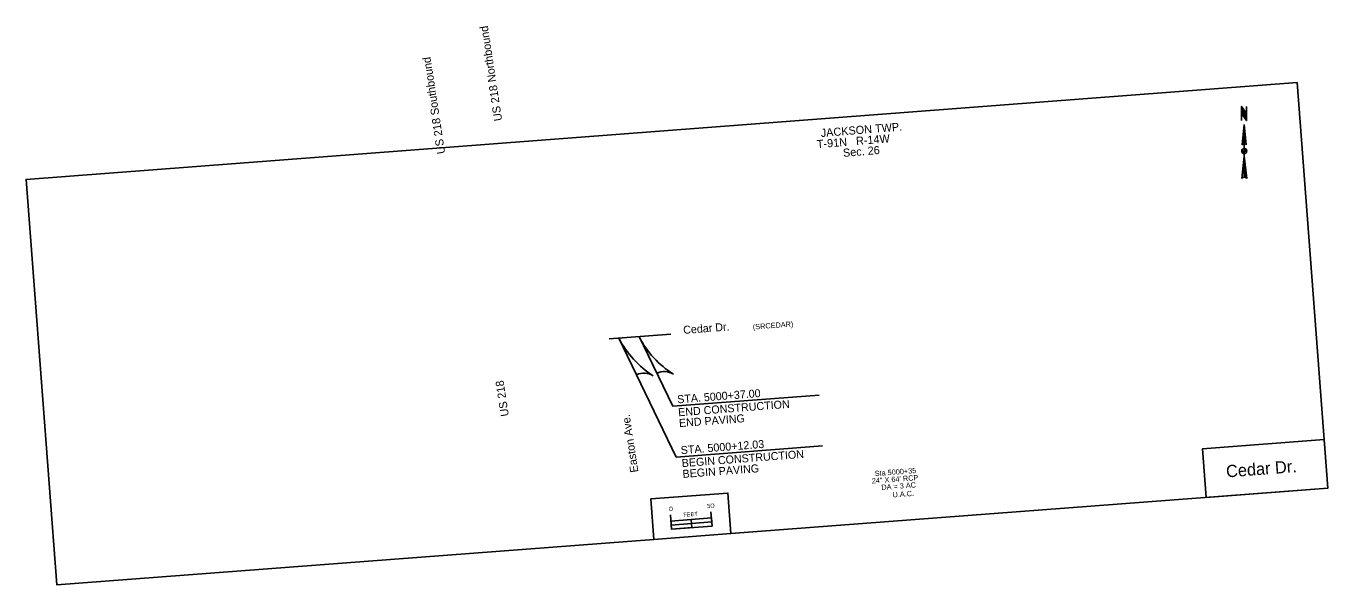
# Model space of a CAD drawing. Extents: x 5197058 to 5310156, y 3593077 to 3706690.
# Drawn here: x 5197058 to 5198659, y 3706003 to 3706690 of the extents above; entities that cross this region are included whole.
import ezdxf

# ---------------------------------------------------------------- set-up
doc = ezdxf.new("R2010")
doc.units = 0
for name, color, linetype in [('dsnAlignment', 7, 'Continuous'), ('dsnCellsScaleBlock', 7, 'Continuous'), ('dsnNonPlotable', 7, 'Continuous'), ('dsnTextCulvertProp', 7, 'Continuous'), ('dsnTextNote', 7, 'Continuous'), ('dsnTextOverlapEven', 7, 'Continuous'), ('dsnTextOverlapOdd', 7, 'Continuous'), ('phoTxtDrainage', 7, 'Continuous'), ('phoTxtTownSecRange', 7, 'Continuous')]:
    doc.layers.add(name, color=color, linetype=linetype)

msp = doc.modelspace()

# ---------------------------------------------------------------- linework, layer by layer
at = {"layer": 'dsnAlignment'}
msp.add_line((5197774.9, 3706305.5), (5197850.9, 3706311.3), dxfattribs=at)
at = {"layer": 'dsnCellsScaleBlock'}
msp.add_line((5197876.6, 3706073.6), (5197875.8, 3706083.5), dxfattribs=at)
msp.add_line((5197876.6, 3706073.6), (5197875.8, 3706083.5), dxfattribs=at)
for points in [[(5197826.2, 3706108.8), (5197921, 3706116), (5197924.7, 3706066.2), (5197830, 3706059)], [(5197826.2, 3706108.8), (5197921, 3706116), (5197924.7, 3706066.2), (5197830, 3706059)], [(5197876.2, 3706078.6), (5197901.1, 3706080.5), (5197900.7, 3706085.4), (5197875.8, 3706083.5)], [(5197851.6, 3706071.7), (5197876.6, 3706073.6), (5197876.2, 3706078.6), (5197851.2, 3706076.7)]]:
    msp.add_lwpolyline(points, close=True, dxfattribs=at)
for points in [[(5197850.3, 3706089.1), (5197851.6, 3706071.7), (5197901.5, 3706075.5), (5197900.2, 3706092.9)], [(5197850.9, 3706081.6), (5197900.7, 3706085.4)]]:
    msp.add_lwpolyline(points, dxfattribs=at)
at = {"layer": 'dsnNonPlotable'}
msp.add_lwpolyline([(5197924.7, 3706066.2), (5197921, 3706116), (5197826.2, 3706108.8), (5197830, 3706059), (5197095.9, 3706003.1), (5197057.9, 3706501.6), (5198620.9, 3706620.6), (5198658.9, 3706122.1)], close=True, dxfattribs=at)
at = {"layer": 'dsnTextNote'}
for p, q in [((5197786.9, 3706306.4), (5197857.5, 3706160.3)), ((5197808.7, 3706261.4), (5197786.9, 3706306.4)), ((5197787.2, 3706305.8), (5197787.1, 3706306)), ((5197811.8, 3706308.3), (5197853.1, 3706222.8)), ((5197833.5, 3706263.3), (5197811.8, 3706308.3)), ((5197812.1, 3706307.7), (5197812, 3706307.9)), ((5197808.7, 3706261.4), (5197808.7, 3706261.4)), ((5197833.5, 3706263.3), (5197833.5, 3706263.3)), ((5197853.1, 3706222.8), (5198033.1, 3706236.5)), ((5197857.5, 3706160.3), (5198037.5, 3706174))]:
    msp.add_line(p, q, dxfattribs=at)
for centre, radius, start, end in [((5197894.2, 3706362.2), 121, 207.4727, 237.5027), ((5197919.1, 3706364.1), 121, 207.4727, 237.5027), ((5197817.9, 3706242.3), 21.2, 57.5023, 115.7876), ((5197842.8, 3706244.2), 21.2, 57.5023, 115.7876)]:
    msp.add_arc(centre, radius, start, end, dxfattribs=at)
at = {"layer": 'dsnTextOverlapEven'}
for points in [[(5198658.9, 3706122.1), (5198509.3, 3706110.7), (5198504.8, 3706170.5), (5198654.3, 3706181.9)], [(5198504.8, 3706170.5), (5198654.3, 3706181.9), (5198658.9, 3706122.1), (5198509.3, 3706110.7)]]:
    msp.add_lwpolyline(points, close=True, dxfattribs=at)
at = {"layer": 'dsnTextOverlapOdd'}
for p, q in [((5198555.6, 3706564.9), (5198555.4, 3706563.5)), ((5198553.5, 3706544.2), (5198553.9, 3706544.7)), ((5198552.8, 3706536.5), (5198559, 3706536.5))]:
    msp.add_line(p, q, dxfattribs=at)
for points in [[(5198552.7, 3706573.8), (5198552.7, 3706591.3)], [(5198558.9, 3706591.3), (5198558.9, 3706573.8), (5198552.7, 3706582.5), (5198552.7, 3706591.3), (5198558.9, 3706582.6)], [(5198552.9, 3706590.4), (5198552.9, 3706582.6), (5198558.7, 3706574.6), (5198558.6, 3706582.5), (5198553.2, 3706589.8), (5198553.3, 3706582.7), (5198558.5, 3706575.5), (5198558.3, 3706582.5), (5198553.4, 3706589.1), (5198553.4, 3706582.8), (5198558.2, 3706576), (5198558, 3706582.5), (5198553.6, 3706588.4), (5198553.7, 3706582.7), (5198558, 3706576.7), (5198557.7, 3706582.4), (5198553.8, 3706587.7), (5198553.8, 3706582.8), (5198557.8, 3706577.4), (5198557.5, 3706582.3), (5198554, 3706586.9), (5198554.1, 3706582.8), (5198557.5, 3706578.4), (5198557.3, 3706582.2), (5198554.3, 3706586.2), (5198554.2, 3706582.9), (5198557.2, 3706579.1), (5198557, 3706582.3), (5198554.5, 3706585.4), (5198554.4, 3706582.8), (5198556.9, 3706579.9), (5198556.7, 3706582.2), (5198554.6, 3706584.8), (5198554.7, 3706582.7), (5198556.6, 3706580.4), (5198556.5, 3706582.1), (5198554.8, 3706584.2), (5198554.8, 3706582.7), (5198556.3, 3706581.1), (5198556.2, 3706582.2), (5198555.1, 3706583.4), (5198555.1, 3706582.7), (5198556, 3706581.7), (5198556.1, 3706582.1), (5198555.3, 3706582.9), (5198555.2, 3706582.7), (5198555.8, 3706582), (5198555.9, 3706582.2)], [(5198553.4, 3706544), (5198555.8, 3706568.9)], [(5198555.7, 3706566.6), (5198555.6, 3706545.4), (5198554.6, 3706545.1), (5198553.8, 3706544.7), (5198553.6, 3706544.5), (5198555.6, 3706564.2), (5198555.4, 3706545.5), (5198553.8, 3706544.9), (5198555.4, 3706561.6), (5198555.2, 3706545.6), (5198554, 3706545.1), (5198555.2, 3706558.5), (5198555.1, 3706545.6), (5198554.1, 3706545.4), (5198555, 3706555.2), (5198554.8, 3706545.7), (5198554.3, 3706545.5), (5198554.8, 3706552.4), (5198554.6, 3706545.8), (5198554.4, 3706545.7), (5198554.6, 3706548.2)], [(5198555.8, 3706568.9), (5198556, 3706504.2)], [(5198555.8, 3706568.9), (5198558.4, 3706544)], [(5198552.8, 3706536.4), (5198555.8, 3706536.4), (5198555.8, 3706533.5), (5198555, 3706533.6), (5198553.9, 3706534.2), (5198553.3, 3706534.9), (5198553, 3706535.5), (5198552.8, 3706536.1), (5198552.8, 3706536.4), (5198552.8, 3706536.4), (5198555.7, 3706536.4), (5198555.8, 3706533.6), (5198554.4, 3706533.9), (5198553.5, 3706534.5), (5198553.1, 3706535.2), (5198552.9, 3706535.8), (5198552.9, 3706536.3), (5198555.7, 3706536.3), (5198555.7, 3706533.6), (5198555.6, 3706533.4), (5198554.6, 3706533.8), (5198554.1, 3706534), (5198553.6, 3706534.5), (5198552.9, 3706536.2), (5198555.6, 3706536.2), (5198555.7, 3706533.6), (5198555.7, 3706533.4), (5198555.2, 3706533.5), (5198554.8, 3706533.6), (5198553.4, 3706534.9), (5198553.2, 3706535.3), (5198552.9, 3706536), (5198553, 3706536.1), (5198555.5, 3706536.1), (5198555.6, 3706533.6), (5198555.2, 3706533.6), (5198555, 3706533.7), (5198554.2, 3706534), (5198553.5, 3706534.6), (5198553.4, 3706534.9), (5198553, 3706535.9), (5198553, 3706536.1), (5198555.4, 3706536.1), (5198555.5, 3706533.7), (5198554.5, 3706533.9), (5198553.5, 3706534.8), (5198553.1, 3706536), (5198555.4, 3706536), (5198555.5, 3706533.7), (5198554.5, 3706533.9), (5198553.5, 3706534.8), (5198553.1, 3706535.9), (5198555.3, 3706535.9), (5198555.4, 3706533.8), (5198554.5, 3706534), (5198553.6, 3706534.8), (5198553.2, 3706535.8), (5198555.2, 3706535.8), (5198555.3, 3706533.9), (5198554.5, 3706534), (5198553.6, 3706534.8), (5198553.3, 3706535.8), (5198555.2, 3706535.8), (5198555.2, 3706533.9), (5198554.5, 3706534.1), (5198553.2, 3706535.7), (5198555.1, 3706535.7), (5198555.2, 3706534), (5198554.2, 3706534.3), (5198553.4, 3706535.6), (5198555, 3706535.6), (5198555.1, 3706534.1), (5198553.7, 3706534.8), (5198553.7, 3706534.8), (5198553.5, 3706535.5), (5198555, 3706535.5), (5198555, 3706534.2), (5198554.5, 3706534.1), (5198553.9, 3706534.6), (5198553.7, 3706534.8), (5198553.6, 3706535.4), (5198554.9, 3706535.4), (5198555, 3706534.3), (5198554.7, 3706534.1), (5198554.3, 3706534.3), (5198553.8, 3706534.8), (5198553.7, 3706535.3), (5198554.8, 3706535.4), (5198554.8, 3706534.3), (5198554.5, 3706534.3), (5198553.8, 3706535), (5198553.7, 3706535.2), (5198554.8, 3706535.3), (5198554.8, 3706534.4), (5198554.1, 3706534.6), (5198553.8, 3706535.2), (5198554.7, 3706535.2), (5198554.7, 3706534.5), (5198554.1, 3706534.7), (5198553.9, 3706535.1), (5198554.6, 3706535.1)], [(5198559.1, 3706502.9), (5198555.9, 3706530.3), (5198552.9, 3706502.9)], [(5198554.6, 3706535.1), (5198554.6, 3706534.5), (5198554.2, 3706534.7), (5198554, 3706535), (5198554.5, 3706535.1), (5198554.6, 3706534.6), (5198554.2, 3706534.7), (5198554.1, 3706535), (5198554.5, 3706535), (5198554.5, 3706534.7), (5198554.3, 3706534.8), (5198554.2, 3706534.9), (5198554.4, 3706534.9), (5198554.4, 3706534.8), (5198554.3, 3706534.8), (5198554.3, 3706534.9), (5198554.4, 3706534.8)], [(5198558.9, 3706536.6), (5198555.9, 3706536.6), (5198555.9, 3706539.5), (5198556.8, 3706539.4), (5198557.8, 3706538.8), (5198558.4, 3706538.1), (5198558.8, 3706537.5), (5198558.9, 3706536.9), (5198558.9, 3706536.6), (5198558.9, 3706536.6), (5198556, 3706536.6), (5198556, 3706539.4), (5198557.4, 3706539.1), (5198558.2, 3706538.5), (5198558.6, 3706537.8), (5198558.9, 3706537.2), (5198558.9, 3706536.7), (5198556.1, 3706536.7), (5198556, 3706539.4), (5198556.1, 3706539.6), (5198557.2, 3706539.2), (5198557.7, 3706539), (5198558.2, 3706538.5), (5198558.8, 3706536.8), (5198556.2, 3706536.8), (5198556.1, 3706539.4), (5198556, 3706539.6), (5198556.5, 3706539.5), (5198557, 3706539.3), (5198558.4, 3706538.1), (5198558.6, 3706537.7), (5198558.8, 3706537), (5198558.8, 3706536.9), (5198556.2, 3706536.9), (5198556.2, 3706539.4), (5198556.5, 3706539.4), (5198556.8, 3706539.3), (5198557.5, 3706539), (5198558.2, 3706538.4), (5198558.4, 3706538.1), (5198558.8, 3706537.1), (5198558.7, 3706536.9), (5198556.3, 3706536.9), (5198556.2, 3706539.3), (5198557.3, 3706539.1), (5198558.2, 3706538.2), (5198558.7, 3706537), (5198556.4, 3706537), (5198556.3, 3706539.3), (5198557.3, 3706539), (5198558.2, 3706538.2), (5198558.6, 3706537.1), (5198556.5, 3706537.1), (5198556.4, 3706539.2), (5198557.3, 3706539), (5198558.2, 3706538.2), (5198558.5, 3706537.1), (5198556.5, 3706537.1), (5198556.5, 3706539.1), (5198557.3, 3706539), (5198558.1, 3706538.2), (5198558.4, 3706537.2), (5198556.6, 3706537.2), (5198556.5, 3706539.1), (5198557.3, 3706538.9), (5198558.6, 3706537.3), (5198556.6, 3706537.3), (5198556.6, 3706539), (5198557.6, 3706538.7), (5198558.3, 3706537.4), (5198556.7, 3706537.4), (5198556.6, 3706538.9), (5198558.1, 3706538.2), (5198558.1, 3706538.2), (5198558.2, 3706537.5), (5198556.8, 3706537.4), (5198556.7, 3706538.8), (5198557.2, 3706538.9), (5198557.8, 3706538.4), (5198558, 3706538.2), (5198558.1, 3706537.6), (5198556.9, 3706537.5), (5198556.8, 3706538.7), (5198557, 3706538.9), (5198557.4, 3706538.6), (5198557.9, 3706538.2), (5198558.1, 3706537.7), (5198556.9, 3706537.6), (5198556.9, 3706538.7), (5198557.2, 3706538.7), (5198557.9, 3706538), (5198558, 3706537.7), (5198557, 3706537.7), (5198557, 3706538.6), (5198557.7, 3706538.3), (5198558, 3706537.8), (5198557.1, 3706537.8), (5198557.1, 3706538.5), (5198557.7, 3706538.3), (5198557.8, 3706537.9), (5198557.1, 3706537.9)], [(5198556.1, 3706528.2), (5198556, 3706527), (5198556.1, 3706527.2), (5198556.1, 3706528.3)], [(5198557.1, 3706537.9), (5198557.1, 3706538.5), (5198557.6, 3706538.3), (5198557.8, 3706537.9), (5198557.2, 3706537.9), (5198557.2, 3706538.4), (5198557.5, 3706538.3), (5198557.7, 3706538), (5198557.3, 3706538), (5198557.3, 3706538.3), (5198557.5, 3706538.2), (5198557.6, 3706538.1), (5198557.4, 3706538.1), (5198557.3, 3706538.2), (5198557.4, 3706538.2), (5198557.4, 3706538.1), (5198557.3, 3706538.2)], [(5198556.1, 3706526.6), (5198558.7, 3706503.7), (5198556.2, 3706504.3), (5198556, 3706527.1), (5198558.8, 3706503.4), (5198557.6, 3706504.5), (5198557.3, 3706504.2), (5198556.5, 3706504.3), (5198557.9, 3706504)], [(5198556.2, 3706525.8), (5198556.3, 3706504.6), (5198557.3, 3706504.3), (5198558.2, 3706503.9), (5198558.4, 3706503.8), (5198556.3, 3706523.5), (5198556.5, 3706504.8), (5198558.2, 3706504.1), (5198556.5, 3706520.8), (5198556.7, 3706504.8), (5198558, 3706504.4), (5198556.7, 3706517.7), (5198556.9, 3706504.8), (5198557.9, 3706504.6), (5198556.9, 3706514.5), (5198557.2, 3706505), (5198557.7, 3706504.7), (5198557.1, 3706511.6), (5198557.3, 3706505), (5198557.5, 3706504.9), (5198557.3, 3706507.4)]]:
    msp.add_lwpolyline(points, dxfattribs=at)
msp.add_circle((5198555.9, 3706536.5), 3.11, dxfattribs=at)
for centre, radius, start, end in [((5198555.9, 3706542.1), 3.11, 36.9944, 143.2546), ((5198556, 3706499.7), 4.51, 46.5217, 133.7273)]:
    msp.add_arc(centre, radius, start, end, dxfattribs=at)

# ---------------------------------------------------------------- texts
at = {"layer": 'dsnCellsScaleBlock'}
for s, p in [('O', (5197848.3, 3706094)), ('5O', (5197895.7, 3706097.6)), ('FEET', (5197866.5, 3706086.8))]:
    msp.add_text(s, height=5, rotation=4.3536, dxfattribs=at).set_placement(p)
at = {"layer": 'dsnTextCulvertProp'}
msp.add_text('U.A.C.', height=6.5, rotation=4.3019, dxfattribs=at).set_placement((5198123.7, 3706110.6))
at = {"layer": 'dsnTextNote'}
for s, height, rotation, p in [('US 218 Northbound', 10, 98.6831, (5197643.5, 3706574.1)), ('US 218 Southbound', 10, 98.6831, (5197573.4, 3706533.6)), ('Cedar Dr. ', 9.84, 4.3536, (5197866.4, 3706311.6)), ('(SRCEDAR)', 6.5, 4.3536, (5197951.9, 3706317)), ('US 218', 10, 98.6831, (5197651.7, 3706211)), ('STA. 5000+37.00', 9.843, 4.3536, (5197859, 3706226.3)), ('END CONSTRUCTION', 9.843, 4.3536, (5197860.2, 3706210.4)), ('Easton Ave.', 10, 98.6831, (5197811, 3706142.1)), ('END PAVING', 9.84, 4.3536, (5197861.2, 3706197.1)), ('STA. 5000+12.03', 9.843, 4.3536, (5197863.4, 3706163.8)), ('BEGIN CONSTRUCTION', 9.843, 4.3536, (5197864.6, 3706147.9)), ('BEGIN PAVING', 9.843, 4.3536, (5197865.6, 3706134.6))]:
    msp.add_text(s, height=height, rotation=rotation, dxfattribs=at).set_placement(p)
at = {"layer": 'dsnTextOverlapEven'}
msp.add_text('Cedar Dr.', height=15, rotation=4.3536, dxfattribs=at).set_placement((5198534.2, 3706135.2))
at = {"layer": 'phoTxtDrainage'}
for s, p in [('Sta 5000+35', (5198101.8, 3706136.8)), ('24" X 64\' RCP', (5198098.2, 3706127.7)), ('DA = 3 AC', (5198109.9, 3706119.8))]:
    msp.add_text(s, height=6.5, rotation=4.3019, dxfattribs=at).set_placement(p)
at = {"layer": 'phoTxtTownSecRange'}
for s, p in [('JACKSON TWP. ', (5198035.6, 3706553.6)), ('T-91N   R-14W ', (5198030.8, 3706539.9)), ('Sec. 26', (5198062.9, 3706529.2))]:
    msp.add_text(s, height=10, rotation=4.6484, dxfattribs=at).set_placement(p)

doc.saveas('drawing.dxf')
